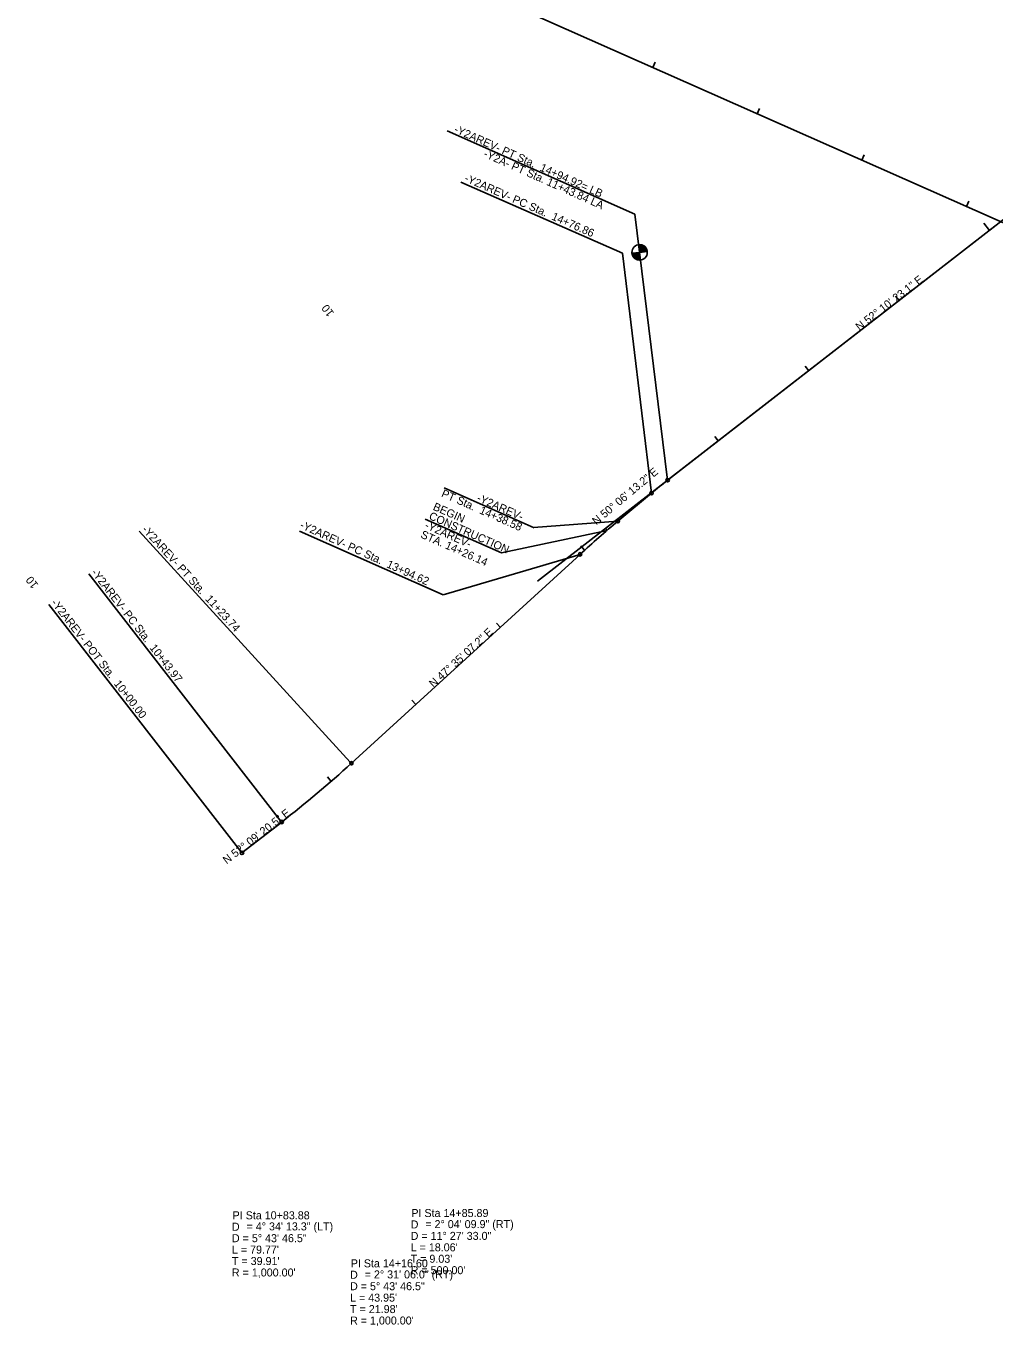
# Model space of a CAD drawing. Extents: x 1636713 to 1642889, y 841520 to 844630.
# Drawn here: x 1638664 to 1639512, y 842034 to 843171 of the extents above; entities that cross this region are included whole.
import ezdxf

# ---------------------------------------------------------------- set-up
doc = ezdxf.new("R2010")
doc.units = 0
for name, color, linetype in [('Exist 4 AWG with gnd feeder circuit in conduit', 7, 'Continuous'), ('Exist 6 AWG with gnd feeder circuit', 7, 'Continuous'), ('Exist 8 AWG with gnd feeder circuit', 7, 'Continuous'), ('Exist 8 AWG with gnd feeder circuit in conduit', 7, 'Continuous'), ('Prop 2 AWG with gnd feeder circuit', 7, 'Continuous'), ('Prop 2 AWG with gnd feeder circuit in conduit', 7, 'Continuous'), ('Prop 4 AWG with gnd feeder circuit', 7, 'Continuous'), ('Prop Berm Ditch Leader', 7, 'Continuous'), ('Prop Clearing and Grubbing', 7, 'Continuous')]:
    doc.layers.add(name, color=color, linetype=linetype)

msp = doc.modelspace()

# ---------------------------------------------------------------- linework, layer by layer
at = {"layer": 'Exist 6 AWG with gnd feeder circuit'}
for p, q in [((1639196.7, 843006.2), (1639032.6, 843079)), ((1639185.9, 842972), (1639044.6, 843034.2)), ((1639225.3, 842773.5), (1639196.7, 843006.2)), ((1639211.2, 842762.1), (1639185.9, 842972)), ((1639194.1, 842971.9), (1639200.8, 842972.7)), ((1639200.8, 842972.7), (1639200, 842979.3)), ((1639207.4, 842973.5), (1639200.8, 842972.7)), ((1639201.6, 842966), (1639200.8, 842972.7)), ((1639200.8, 842972.7), (1639201.6, 842966)), ((1639013.4, 842739.5), (1639079.9, 842709.8)), ((1639181.8, 842737.6), (1639108.1, 842732.1)), ((1638947.7, 842527), (1638763.3, 842729)), ((1639079.9, 842709.8), (1639172.3, 842729.5)), ((1639148.7, 842708.6), (1639029.1, 842673.2)), ((1638886.9, 842475.7), (1638719.1, 842691.7)), ((1638852.1, 842448.7), (1638684.3, 842664.7))]:
    msp.add_line(p, q, dxfattribs=at)
for points in [[(1639194.1, 842971.9), (1639194.2, 842971.1)], [(1639194.3, 842971.9), (1639194.4, 842970.4)], [(1639194.4, 842971.9), (1639194.6, 842969.9)], [(1639194.5, 842971.9), (1639194.8, 842969.5)], [(1639194.7, 842971.9), (1639195, 842969.2)], [(1639194.8, 842971.9), (1639195.2, 842969)], [(1639194.9, 842972), (1639195.3, 842968.7)], [(1639195.1, 842972), (1639195.5, 842968.5)], [(1639195.2, 842972), (1639195.6, 842968.3)], [(1639195.3, 842972), (1639195.8, 842968.1)], [(1639195.5, 842972), (1639196, 842968)], [(1639195.6, 842972), (1639196.1, 842967.8)], [(1639195.7, 842972.1), (1639196.3, 842967.7)], [(1639195.9, 842972.1), (1639196.4, 842967.6)], [(1639196, 842972.1), (1639196.6, 842967.4)], [(1639196.1, 842972.1), (1639196.7, 842967.3)], [(1639196.3, 842972.1), (1639196.9, 842967.2)], [(1639196.4, 842972.1), (1639197, 842967.1)], [(1639196.5, 842972.2), (1639197.2, 842967)], [(1639196.7, 842972.2), (1639197.3, 842966.9)], [(1639196.8, 842972.2), (1639197.4, 842966.8)], [(1639196.9, 842972.2), (1639197.6, 842966.7)], [(1639197.1, 842972.2), (1639197.7, 842966.7)], [(1639197.2, 842972.2), (1639197.9, 842966.6)], [(1639197.3, 842972.2), (1639198, 842966.5)], [(1639197.5, 842972.3), (1639198.2, 842966.5)], [(1639197.6, 842972.3), (1639198.3, 842966.4)], [(1639197.7, 842972.3), (1639198.4, 842966.4)], [(1639197.9, 842972.3), (1639198.6, 842966.3)], [(1639198, 842972.3), (1639198.7, 842966.3)], [(1639198.1, 842972.3), (1639198.9, 842966.2)], [(1639198.3, 842972.4), (1639199, 842966.2)], [(1639198.4, 842972.4), (1639199.1, 842966.1)], [(1639198.5, 842972.4), (1639199.3, 842966.1)], [(1639198.7, 842972.4), (1639199.4, 842966.1)], [(1639198.8, 842972.4), (1639199.6, 842966.1)], [(1639198.9, 842972.4), (1639199.7, 842966)], [(1639199.1, 842972.5), (1639199.8, 842966)], [(1639199.2, 842972.5), (1639200, 842966)], [(1639199.3, 842972.5), (1639200.1, 842966)], [(1639199.5, 842972.5), (1639200.3, 842966)], [(1639199.6, 842972.5), (1639200.4, 842966)], [(1639199.7, 842972.5), (1639200.5, 842966)], [(1639199.9, 842972.6), (1639200.7, 842965.9)], [(1639200, 842979.3), (1639200, 842979.3), (1639200.8, 842972.7)], [(1639200, 842972.6), (1639200.8, 842965.9)], [(1639200.1, 842972.6), (1639200.9, 842965.9)], [(1639200.2, 842979.3), (1639201, 842972.7)], [(1639200.3, 842979.3), (1639201.1, 842972.7)], [(1639200.3, 842972.6), (1639201.1, 842965.9)], [(1639200.4, 842979.4), (1639201.2, 842972.7)], [(1639200.4, 842972.6), (1639201.2, 842966)], [(1639200.5, 842972.6), (1639201.3, 842966)], [(1639200.6, 842979.4), (1639201.4, 842972.7)], [(1639200.7, 842979.4), (1639201.5, 842972.7)], [(1639200.7, 842972.6), (1639201.5, 842966), (1639201.5, 842966)], [(1639200.8, 842979.4), (1639201.6, 842972.8)], [(1639201, 842979.4), (1639201.8, 842972.8)], [(1639201.1, 842979.4), (1639201.9, 842972.8)], [(1639201.2, 842979.4), (1639202, 842972.8)], [(1639201.4, 842979.3), (1639202.2, 842972.8)], [(1639201.5, 842979.3), (1639202.3, 842972.8)], [(1639201.7, 842979.3), (1639202.4, 842972.9)], [(1639201.8, 842979.3), (1639202.6, 842972.9)], [(1639201.9, 842979.3), (1639202.7, 842972.9)], [(1639202.1, 842979.2), (1639202.8, 842972.9)], [(1639202.2, 842979.2), (1639203, 842972.9)], [(1639202.3, 842979.2), (1639203.1, 842972.9)], [(1639202.5, 842979.1), (1639203.2, 842973)], [(1639202.6, 842979.1), (1639203.4, 842973)], [(1639202.8, 842979.1), (1639203.5, 842973)], [(1639202.9, 842979), (1639203.6, 842973)], [(1639203, 842979), (1639203.8, 842973)], [(1639203.2, 842978.9), (1639203.9, 842973)], [(1639203.3, 842978.9), (1639204, 842973.1)], [(1639203.5, 842978.8), (1639204.2, 842973.1)], [(1639203.6, 842978.7), (1639204.3, 842973.1)], [(1639203.8, 842978.7), (1639204.4, 842973.1)], [(1639203.9, 842978.6), (1639204.6, 842973.1)], [(1639204, 842978.5), (1639204.7, 842973.1)], [(1639204.2, 842978.4), (1639204.8, 842973.1)], [(1639204.3, 842978.3), (1639205, 842973.2)], [(1639204.5, 842978.2), (1639205.1, 842973.2)], [(1639204.6, 842978.1), (1639205.2, 842973.2)], [(1639204.8, 842978), (1639205.4, 842973.2)], [(1639204.9, 842977.9), (1639205.5, 842973.2)], [(1639205.1, 842977.8), (1639205.6, 842973.2)], [(1639205.2, 842977.7), (1639205.8, 842973.3)], [(1639205.4, 842977.5), (1639205.9, 842973.3)], [(1639205.5, 842977.4), (1639206, 842973.3)], [(1639205.7, 842977.2), (1639206.2, 842973.3)], [(1639205.8, 842977), (1639206.3, 842973.3)], [(1639206, 842976.8), (1639206.4, 842973.3)], [(1639206.2, 842976.6), (1639206.6, 842973.4)], [(1639206.3, 842976.4), (1639206.7, 842973.4)], [(1639206.5, 842976.2), (1639206.8, 842973.4)], [(1639206.7, 842975.9), (1639207, 842973.4)], [(1639206.8, 842975.5), (1639207.1, 842973.4)], [(1639207, 842975.1), (1639207.2, 842973.4)], [(1639207.2, 842974.4), (1639207.4, 842973.5)], [(1639030, 842766.7), (1639108.6, 842731.9)], [(1638903.4, 842728.9), (1639029.1, 842673.2)]]:
    msp.add_lwpolyline(points, dxfattribs=at)
for centre, radius in [((1639200.8, 842972.7), 6.71), ((1639225.3, 842773.5), 1.5), ((1639211.2, 842762.1), 1.5), ((1639181.8, 842737.6), 1.5), ((1639148.7, 842708.6), 1.5), ((1638948.8, 842525.9), 1.5), ((1638887.8, 842474.5), 1.5), ((1638853.1, 842447.6), 1.5)]:
    msp.add_circle(centre, radius, dxfattribs=at)
for start, end in [(186.8391, 276.8391), (6.8391, 96.8391)]:
    msp.add_arc((1639200.8, 842972.7), 6.71, start, end, dxfattribs=at)
at = {"layer": 'Exist 8 AWG with gnd feeder circuit'}
for p, q in [((1638900.9, 843272.5), (1640357.9, 842626.5)), ((1639225.3, 842773.5), (1639731.3, 843166.3)), ((1639181.8, 842737.6), (1639211.2, 842762.1)), ((1638948.8, 842525.9), (1639148.7, 842708.6)), ((1638853.1, 842447.6), (1638887.8, 842474.5))]:
    msp.add_line(p, q, dxfattribs=at)
for centre, radius, start, end in [((1639531.9, 842378.5), 500, 127.8269, 129.8963), ((1639823.2, 841970.4), 1000, 129.8963, 132.4147), ((1638274.3, 843264.2), 1000, 307.8443, 312.4147)]:
    msp.add_arc(centre, radius, start, end, dxfattribs=at)
at = {"layer": 'Prop 2 AWG with gnd feeder circuit in conduit'}
for p, q in [((1639506.6, 842991.9), (1639501.7, 842998.2)), ((1638853.1, 842447.6), (1638848.1, 842453.9))]:
    msp.add_line(p, q, dxfattribs=at)
at = {"layer": 'Prop 4 AWG with gnd feeder circuit'}
for p, q in [((1639212.3, 843134.4), (1639214.3, 843139)), ((1639303.7, 843093.9), (1639305.7, 843098.5)), ((1639395.1, 843053.3), (1639397.2, 843057.9)), ((1639486.5, 843012.8), (1639488.6, 843017.4)), ((1639427.6, 842930.5), (1639424.5, 842934.5)), ((1639348.6, 842869.2), (1639345.5, 842873.2)), ((1639269.6, 842807.9), (1639266.6, 842811.8)), ((1639152.7, 842712.3), (1639149.4, 842716)), ((1639078.9, 842644.8), (1639075.5, 842648.5)), ((1639005.1, 842577.4), (1639001.7, 842581.1)), ((1638931, 842510.1), (1638927.8, 842513.9))]:
    msp.add_line(p, q, dxfattribs=at)
at = {"layer": 'Prop Berm Ditch Leader'}
msp.add_line((1639111.6, 842685.2), (1639731.3, 843166.3), dxfattribs=at)
at = {"layer": 'Prop Clearing and Grubbing'}
msp.add_line((1639170.9, 842731.2), (1639172.3, 842729.5), dxfattribs=at)

# ---------------------------------------------------------------- texts
at = {"layer": 'Exist 4 AWG with gnd feeder circuit in conduit'}
for rotation, p in [(127.8269, (1638934, 842919.7)), (127.8443, (1638675.4, 842682))]:
    msp.add_text('10', height=7, rotation=rotation, dxfattribs=at).set_placement(p)
at = {"layer": 'Exist 6 AWG with gnd feeder circuit'}
for s, rotation, p in [('-Y2AREV- PT Sta.  14+94.92= LB', 335.9473, (1639037.9, 843077.9)), ('-Y2A- PT Sta. 11+43.84 LA', 335.9473, (1639063.7, 843056.5)), ('-Y2AREV- PC Sta.  14+76.86', 336.2667, (1639047, 843035.1)), ('PT Sta.  14+38.58', 336.2348, (1639026.8, 842759.3)), ('-Y2AREV- ', 336.2348, (1639057.8, 842755.4)), ('CONSTRUCTION ', 336.0871, (1639015.9, 842739.7)), ('BEGIN ', 336.0871, (1639019.5, 842747.8)), ('-Y2AREV- PT Sta.  11+23.74', 312.4147, (1638765.1, 842729.9)), ('-Y2AREV- PC Sta.  13+94.62', 335.624, (1638903.1, 842731.9)), ('-Y2AREV- ', 336.0871, (1639012.3, 842731.6)), ('STA. 14+26.14', 336.0871, (1639008.7, 842723.5)), ('-Y2AREV- PC Sta.  10+43.97', 307.8443, (1638720.9, 842692.5)), ('-Y2AREV- POT Sta.  10+00.00', 307.8443, (1638685.8, 842666))]:
    msp.add_text(s, height=7, rotation=rotation, dxfattribs=at).set_placement(p)
at = {"layer": 'Exist 8 AWG with gnd feeder circuit in conduit'}
for s, rotation, p in [('N 52%%d 10\' 23.1" E', 37.8269, (1639393, 842903.9)), ('N 50%%d 06\' 13.2" E', 39.8963, (1639162.9, 842733.9)), ('N 47%%d 35\' 07.2" E', 42.4147, (1639020.5, 842591.7)), ('N 52%%d 09\' 20.5" E', 37.8443, (1638839.7, 842437.4))]:
    msp.add_text(s, height=7, rotation=rotation, dxfattribs=at).set_placement(p)
at = {"layer": 'Prop 2 AWG with gnd feeder circuit'}
for s, p in [('PI Sta 10+83.88', (1638844.9, 842127.1)), ('PI Sta 14+85.89', (1639001.2, 842129.1)), ('D', (1638844.3, 842117.1)), ('= 4%%d 34\' 13.3" (LT)', (1638857.1, 842117.4)), ('D', (1639000.6, 842119.1)), ('= 2%%d 04\' 09.9" (RT)', (1639013.4, 842119.4)), ('D = 5%%d 43\' 46.5"', (1638844.3, 842107.1)), ('D = 11%%d 27\' 33.0"', (1639000.6, 842109.1)), ("L = 18.06'", (1639000.6, 842099.1)), ("L = 79.77'", (1638844.3, 842097.1)), ("T = 9.03'", (1639000.6, 842089.1)), ("T = 39.91'", (1638844.3, 842087.1)), ("R = 1,000.00'", (1638844.3, 842077.1)), ('PI Sta 14+16.60', (1638948.2, 842085.1)), ("R = 500.00'", (1639000.6, 842079.1)), ('D', (1638947.6, 842075.1)), ('D = 5%%d 43\' 46.5"', (1638947.6, 842065.1)), ('= 2%%d 31\' 06.0" (RT)', (1638960.4, 842075.4)), ("L = 43.95'", (1638947.6, 842055.1)), ("T = 21.98'", (1638947.6, 842045.1)), ("R = 1,000.00'", (1638947.6, 842035.1))]:
    msp.add_text(s, height=7, dxfattribs=at).set_placement(p)

doc.saveas('drawing.dxf')
